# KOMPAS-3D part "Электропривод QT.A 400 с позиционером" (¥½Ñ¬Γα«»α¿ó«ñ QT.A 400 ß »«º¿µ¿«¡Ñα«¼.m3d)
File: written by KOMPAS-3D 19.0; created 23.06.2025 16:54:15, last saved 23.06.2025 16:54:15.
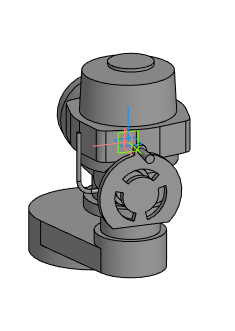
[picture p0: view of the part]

Document properties: Автор: Евгений; Полное имя файла: E:\Dendor Работа Сачек\3D для проектировщиков\3.5 Тип QT.А Электропривод\stp_Электропривод QT.A с позиционером\Электропривод QT.A 400 с позиционером.m3d

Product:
- Part/product: Электропривод QT.A 400 с позиционером

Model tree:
1. Операция без истории:1  (labels: Электропривод QT.A 400 с позиционером)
